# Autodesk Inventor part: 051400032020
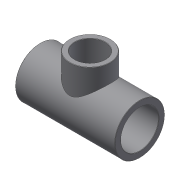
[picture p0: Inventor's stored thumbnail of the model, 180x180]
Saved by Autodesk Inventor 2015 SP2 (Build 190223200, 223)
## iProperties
Created: 2017-10
Part Number: 051400032020
Material: Generic
Description: PLASSON REDUCER TEE - CEMENT PVC 32-20-32
Document SubType Name: Modeling
Designer: KIM
Density: 1 g/cm^3
Appearance: Default
Author: KIM
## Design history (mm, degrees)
derived "051400.ipt"
feature "Solid1::051400.ipt"
feature "Solid2::051400.ipt"
tag "TaggingFeature1"
body "Solid1"
other parameters: "d0" = 78, "d1" = 42, "d2" = 22, "d4" = 32, "d5" = 28.8, "d7" = 0.32, "d8" = 22, "d9" = 33, "d10" = 33, "d12" = 18, "d23" = 16, "d24" = 0.32, "d26" = 0, "d30" = 0, "d32" = 0, "d_" = 32, "E_" = 42, "H_" = 78, "l_" = 22, "Z_" = 14, "E_1" = 33, "l_1" = 16, "Z_1" = 12.5, "H_1" = 54
